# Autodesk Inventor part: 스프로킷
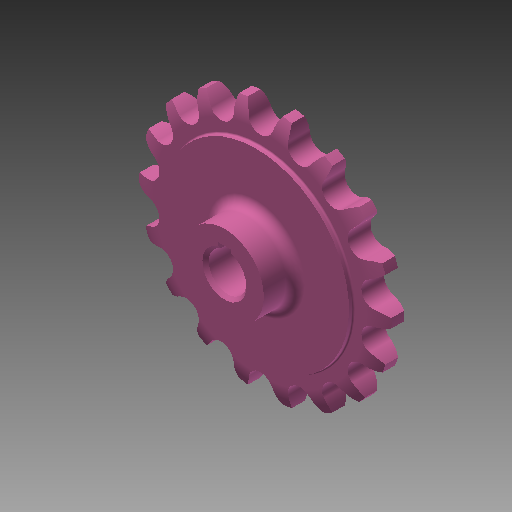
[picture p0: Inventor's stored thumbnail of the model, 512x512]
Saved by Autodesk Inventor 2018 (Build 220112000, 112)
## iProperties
Created: 2016-03
Part Number: 스프로킷
Material: 강철, 탄소
Document SubType Name: Modeling
Designer: mduedu
Density: 7.87 g/cm^3
Mass: 301.818 g
Surface Area: 124.882 cm^2
Volume: 38.3505 cm^3
Appearance: 분홍색
Author: mduedu
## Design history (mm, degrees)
sketch "스케치1"
  geometry: L1 (0, 5)-(29.5, 5); L2 (29.5, 5)-(29.5, 4.1); L3 (30, 3.6)-(33.625, 3.6); L4 (40, 2)-(40, 0); L5 (40, 0)-(0, 0); L6 (0, 0)-(0, 5); L7 (0, -5)-(29.5, -5); L8 (29.5, -5)-(29.5, -4.1); L9 (30, -3.6)-(33.625, -3.6); L10 (40, -2)-(40, 0); L11 (0, 0)-(0, -5); A1 r 13.5 centre (33.625, -9.9) between (40, 2) and (33.625, 3.6); A2 r 13.5 centre (33.625, 9.9) between (33.625, -3.6) and (40, -2); A3 r 0.5 centre (30, 4.1) between (29.5, 4.1) and (30, 3.6); A4 r 0.5 centre (30, -4.1) between (30, -3.6) and (29.5, -4.1); 2 further points
  constraints: 22 end point, 8 point on circle, 6 symmetric about line, 5 tangent, 4 centre point, 4 parallel, 4 point on line, 1 equal radius, 1 horizontal, 1 perpendicular, 1 other
  dimensions: "d0" = 80 diameter of L4 L6; "d2" = 59 diameter of L2 L6; "d3" = 1.6 vertical distance of L4.start L3.end; "d4" = 3.6 distance from line of L4.end L3; "d5" = 5 distance between parallel lines of L5 L1; "d6" = 13.5 radius of A1; "d15" = 0.5 radius of A3
revolve "회전1" sketch "스케치1" stored, may be unused: angle "d7" = 90 deg
sketch "스케치2" dims "d8" = 65.2, "d11" = 80
  geometry: L1 (0, 0)-(0, 32.6); A1 r 36.57 centre (0, 0) between (-16.231, 32.771) and (0, 36.57); A2 r 3.97 centre (0, 36.57) between (-3.866, 35.665) and (0, 32.6); A3 r 12.7 centre (-16.231, 32.771) between (-3.866, 35.665) and (-5.534, 39.615); A4 r 12.7 centre (16.231, 32.771) between (5.534, 39.615) and (3.866, 35.665); A5 r 3.97 centre (0, 36.57) between (0, 32.6) and (3.866, 35.665); A6 r 40 centre (0, 0) between (5.534, 39.615) and (-5.534, 39.615); 2 further points
  constraints: 12 point on circle, 6 centre point, 4 coincident, 3 symmetric about line, 2 end point, 1 point on line, 1 tangent, 1 vertical, 1 vertical alignment, 7 other
  dimensions: "d10" = 73.14 diameter of A1; "d12" = 12.7 radius of A3
extrude "돌출1" cut sketch "스케치2" extent not by distance; stored distance "d13" = 10; taper "d14" = 0 deg
sketch "스케치3"
  geometry: C1 r 12.5 at (0, 0); 1 further point
  constraints: 1 centre point, 1 coincident
  dimensions: "d19" = 25 diameter of C1
extrude "돌출2" join sketch "스케치3" distance "d20" = 10; taper "d21" = 0 deg
fillet "모깎기1" dims "d22" = 3
sketch "스케치4"
  geometry: L1 (-2, 0)-(2, 0); L2 (2, 0)-(2, 7.8); L3 (2, 7.8)-(-2, 7.8); L4 (-2, 7.8)-(-2, 0); C1 r 6 at (0, 0); 2 further points
  constraints: 8 end point, 2 coincident, 2 parallel, 1 centre point, 1 horizontal, 1 midpoint, 1 perpendicular
  dimensions: "d23" = 12 diameter of C1; "d25" = 4 distance of L2.end L3.end; "d26" = 7.8 distance of L1.end L2.end
extrude "돌출3" cut sketch "스케치4" extent not by distance; stored distance "d27" = 8; taper "d28" = 0 deg
chamfer "모따기2" distance "d42" = 1; stored, may be unused: second distance "d43" = 2, angle "d44" = 45 deg
node "솔리드1"
pattern_circular "원형 패턴1" dims angle "d17" = 360 deg
